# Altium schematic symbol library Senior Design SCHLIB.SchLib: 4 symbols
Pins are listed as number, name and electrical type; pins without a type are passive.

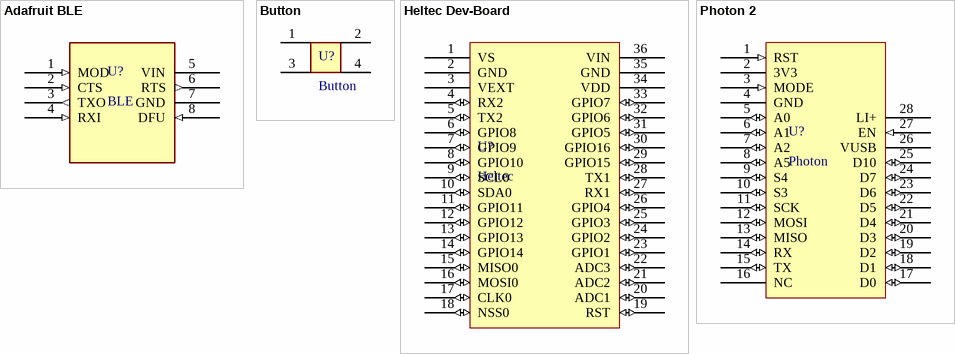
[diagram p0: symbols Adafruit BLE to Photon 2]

## Adafruit BLE
designator U?, comment BLE
footprint Adafruit BLE
pins: 1 MOD (in), 2 CTS (in), 3 TXO (out), 4 RXI (in), 5 VIN (power), 6 RTS (out), 7 GND (power), 8 DFU (in)

## Button
designator U?
footprint BUTTON
pins: 1, 2, 3, 4

## Heltec Dev-Board
designator U?, comment Heltec
footprint HELTEC
pins: 1 VS (power), 2 GND (power), 3 VEXT (power), 4 RX2 (io), 5 TX2 (io), 6 GPIO8 (io), 7 GPIO9 (io), 8 GPIO10 (io), 9 SCL0 (io), 10 SDA0 (io), 11 GPIO11 (io), 12 GPIO12 (io), 13 GPIO13 (io), 14 GPIO14 (io), 15 MISO0 (io), 16 MOSI0 (io), 17 CLK0 (io), 18 NSS0 (io), 19 RST (io), 20 ADC1 (io), 21 ADC2 (io), 22 ADC3 (io), 23 GPIO1 (io), 24 GPIO2 (io), 25 GPIO3 (io), 26 GPIO4 (io), 27 RX1 (io), 28 TX1 (io), 29 GPIO15 (io), 30 GPIO16 (io), 31 GPIO5 (io), 32 GPIO6 (io), 33 GPIO7 (io), 34 VDD (power), 35 GND (power), 36 VIN (power)

## Photon 2
designator U?, comment Photon
Particle Photon 2 IoT Development Board
footprint PCBComponent_1
pins: 1 RST (in), 2 3V3 (power), 3 MODE (in), 4 GND (power), 5 A0 (io), 6 A1 (io), 7 A2 (io), 8 A5 (io), 9 S4 (io), 10 S3 (io), 11 SCK (io), 12 MOSI (io), 13 MISO (io), 14 RX (io), 15 TX (io), 16 NC (power), 17 D0 (io), 18 D1 (io), 19 D2 (io), 20 D3 (io), 21 D4 (io), 22 D5 (io), 23 D6 (io), 24 D7 (io), 25 D10 (io), 26 VUSB (power), 27 EN (in), 28 LI+ (power)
